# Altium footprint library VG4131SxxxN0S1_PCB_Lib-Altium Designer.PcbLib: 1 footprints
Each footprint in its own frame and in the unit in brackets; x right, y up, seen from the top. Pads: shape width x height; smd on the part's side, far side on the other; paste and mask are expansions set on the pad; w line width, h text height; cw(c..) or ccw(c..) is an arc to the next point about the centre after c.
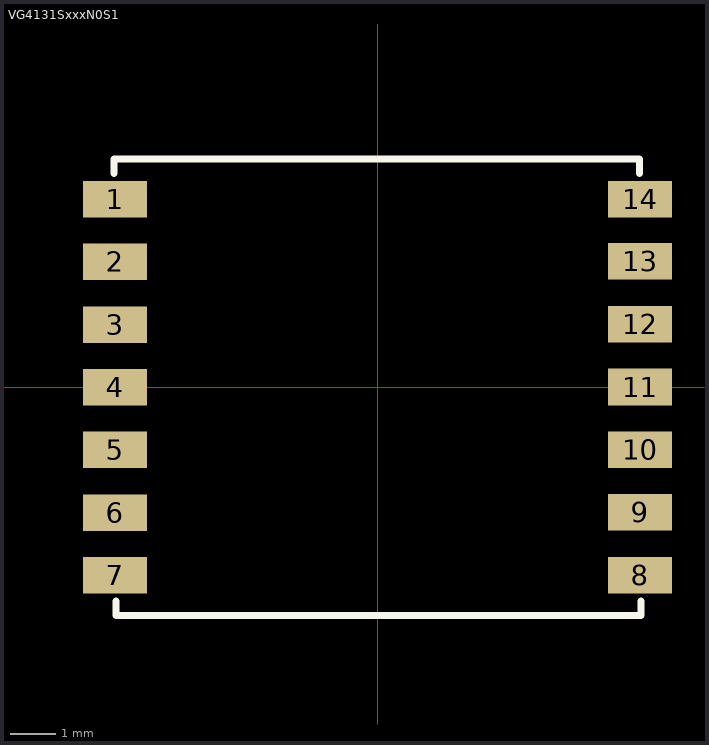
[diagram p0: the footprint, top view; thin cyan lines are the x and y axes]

## VG4131SxxxN0S1 [mm]
pads (15):
  round 1 on Top Overlay: 1(-6.985,5.08)
  rect 1.4x0.8 smd: 1(-5.75,4.12) 2(-5.75,2.747) 3(-5.75,1.373) 4(-5.75,0) 5(-5.75,-1.373) 6(-5.75,-2.747) 7(-5.75,-4.12) 8(5.75,-4.12) 9(5.75,-2.738) 10(5.75,-1.367) 11(5.75,0.005) 12(5.75,1.377) 13(5.75,2.76) 14(5.75,4.12)
Top Overlay:
  lines w0.152: -5.77,4.685 -5.77,5 5.73,5 5.73,4.685 ; -5.73,-4.685 -5.73,-5 5.77,-5 5.77,-4.685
